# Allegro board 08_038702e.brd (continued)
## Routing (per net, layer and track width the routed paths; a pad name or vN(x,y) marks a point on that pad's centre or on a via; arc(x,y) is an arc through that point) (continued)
DDR3_DQ3: length 43.7
  TOP w0.197: U1.G26 v1(41.22,17.59)
  L17_SIG w0.14: v1(56.19,20.31) 56.07,20.31 55.68,19.92 54.54,19.92 54.15,19.54 54.15,15.86 54.92,15.09 54.92,10.78 54.66,10.52 50.09,10.52 49.84,10.78 49.84,11.16 50.09,11.41 53.39,11.41 53.65,11.67 53.65,14.38 53.67,14.4 53.67,15.08 53.14,15.6 53.14,19.67 52.88,19.92 49.33,19.92 48.36,18.95 44.07,18.95 43.85,18.74 43.85,18.64 43.23,18.02 41.64,18.02 v1(41.22,17.59)
  BOTTOM w0.197: U2.F8 v1(56.19,20.31)
DDR3_DQ4: length 43.5
  TOP w0.197: U1.H26 v1(40.22,17.59)
  L3_SIG w0.14: v1(40.22,17.59) 40.22,16.84 41.2,15.86 44.76,15.86 45.77,16.87 45.77,17.76 46.15,18.14 49.2,18.14 49.46,18.4 50.4,18.4 50.44,18.35 56.2,18.35 56.44,18.59 56.44,18.92 56.2,19.16 55.55,19.16 55.54,19.15 49.08,19.15 48.82,19.41 48.82,19.54 49.2,19.92 54.44,19.92 54.66,20.14 54.66,20.46 54.44,20.68 49.84,20.68 49.58,20.94 49.58,21.3 49.84,21.55 51.83,21.55 v1(52.19,21.91)
  BOTTOM w0.197: U2.H3 v1(52.19,21.91)
DDR3_DQ5: length 43.6
  TOP w0.197: U1.H23 v1(40.22,20.59)
  L4_SIG w0.14: v1(40.22,20.59) 40.22,20.59 40.69,21.06 47.3,21.06 47.93,20.43 48.82,20.43 49.46,21.06 49.86,21.06 50.34,21.55 54.52,21.55 55.3,22.33 55.9,22.33 56.72,23.15 57.14,23.15 57.35,23.36 57.35,25.38 57.61,25.64 57.97,25.64 58.22,25.38 58.22,23.73 58.44,23.51 58.63,23.51 58.85,23.73 58.85,24.67 59.19,25 59.66,25 60,24.67 60,24.62 60.38,24.24 61.39,24.24 62.01,23.62 64.19,23.62 64.57,23.24 64.57,22.59 64.19,22.21 62.54,22.21 61.88,22.86 61.88,22.99 61.52,23.35 60,23.35 59.62,22.97 58.22,22.97 57.96,22.71 57.2,22.71 56.95,22.46 56.95,22.38 56.48,21.91 v1(56.19,21.91)
  BOTTOM w0.197: U2.H8 v1(56.19,21.91)
DDR3_DQ6: length 43.4
  TOP w0.197: U1.J24 v1(39.22,19.59)
  L4_SIG w0.14: v1(39.22,19.59) 39.65,19.15 39.67,19.15 39.68,19.16 40.28,19.16 40.82,18.61 40.82,16.24 41.07,15.98 41.84,15.98 41.96,16.11 41.96,16.68 42.15,16.87 42.42,16.87 42.62,16.68 42.62,16.21 42.83,16 42.83,16 42.85,15.98 49.11,15.98 49.33,15.76 49.33,15.44 49.11,15.22 40.57,15.22 39.68,16.11 39.68,17.89 39.42,18.14 39.04,18.14 38.79,18.4 38.79,19.92 39.04,20.17 39.3,20.17 39.55,19.92 40.04,19.92 40.07,19.95 40.37,19.95 40.39,19.92 41.04,19.92 41.07,19.95 41.37,19.95 41.39,19.92 42.04,19.92 42.07,19.95 42.37,19.95 42.39,19.92 43.04,19.92 43.07,19.95 43.37,19.95 43.39,19.92 44.04,19.92 44.07,19.95 44.37,19.95 44.39,19.92 45.04,19.92 45.07,19.95 45.37,19.95 45.39,19.92 46.04,19.92 46.07,19.95 46.37,19.95 46.39,19.92 47.04,19.92 47.07,19.95 47.37,19.95 47.39,19.92 49.21,19.92 49.43,20.14 49.43,20.46 49.64,20.68 49.9,20.68 49.98,20.75 50.23,20.75 v1(50.59,21.11)
  BOTTOM w0.197: U2.G2 v1(50.59,21.11)
DDR3_DQ7: length 43.6
  TOP w0.197: U1.J23 v1(39.22,20.59)
  L17_SIG w0.14: v1(39.22,20.59) 38.8,20.17 32.18,20.17 31.8,19.79 31.8,16.36 31.55,16.11 30.91,16.11 30.89,16.13 30.89,16.13 30.68,16.34 30.68,16.35 30.66,16.36 30.66,20.81 31.08,21.23 36.41,21.23 36.61,21.42 36.87,21.42 37.07,21.23 37.1,21.23 47.37,21.23 47.62,21.48 52.34,21.48 52.37,21.44 52.88,21.44 53.35,21.91 v1(55.39,21.91)
  BOTTOM w0.197: U2.H7 v1(55.39,21.91)
DDR3_DQ8: length 44
  TOP w0.197: U1.K26 v1(38.22,17.59)
  L4_SIG w0.14: v1(38.22,17.59) 38.33,17.59 38.91,17 38.91,16.36 39.3,15.98 39.3,15.73 40.31,14.71 49.33,14.71 49.71,15.09 49.71,15.6 50.09,15.98 50.41,15.98 50.44,15.95 50.74,15.95 50.95,16.16 50.95,16.64 50.85,16.75 48.69,16.75 48.44,17 48.44,17.25 48.69,17.51 51.11,17.51 51.49,17.13 51.49,16.66 51.48,16.65 51.48,15.98 50.85,15.35 50.34,15.35 50.09,15.09 50.09,14.46 50.36,14.19 54,14.19 54.39,14.57 54.39,14.57 54.49,14.67 54.84,14.67 55.3,14.21 56.06,14.21 56.31,14.46 56.31,14.84 56.06,15.09 52.76,15.09 52.63,15.22 52.63,18.4 52.88,18.65 54.34,18.65 54.41,18.71 v1(55.39,18.71)
  BOTTOM w0.197: U2.D7 v1(55.39,18.71)
DDR3_DQ9: length 43.7
  TOP w0.197: U1.L23 v1(37.22,20.59)
  L6_SIG w0.14: v1(37.22,20.59) 36.74,21.06 35.1,21.06 33.71,22.46 33.71,23.73 34.09,24.11 41.45,24.11 41.84,23.73 41.84,21.23 42.12,20.95 42.57,20.95 42.85,21.23 42.85,22.74 43.34,23.23 43.37,23.23 43.58,23.44 43.58,23.44 43.68,23.54 43.68,24.97 43.83,25.13 45.64,25.13 45.85,24.91 45.85,24.37 45.6,24.11 45.14,24.11 44.58,23.55 44.58,23.44 44.37,23.23 44.25,23.23 43.58,22.55 43.58,20.46 43.82,20.23 46.75,20.23 46.97,20 47.72,20 48.57,19.15 50.74,19.15 50.75,19.16 52.04,19.16 52.04,19.15 52.34,19.15 52.35,19.16 53.46,19.16 53.65,18.97 53.65,18.71 53.46,18.52 52.76,18.52 52.63,18.65 52.26,18.65 v1(52.19,18.71)
  BOTTOM w0.197: U2.C3 v1(52.19,18.71)
DDR3_DQ10: length 43.8
  TOP w0.197: U1.M26 v1(36.22,17.59)
  L7_SIG w0.14: v6(56.19,17.94) 56.19,17.91 56.63,17.48 57.07,17.48 57.36,17.76 58.47,17.76 58.73,17.51 58.73,16.75 58.98,16.49 59.23,16.49 59.51,16.77 59.51,17.51 59.76,17.76 60.89,17.76 61.14,18.02 61.14,19.67 60.89,19.92 58.85,19.92 58.47,19.54 58.47,18.78 58.05,18.35 55.93,18.35 55.81,18.23 55.81,17.76 55.55,17.51 55.3,17.51 54.79,17 54.79,15.98 55.04,15.73 55.3,15.73 55.68,15.35 55.68,13.82 55.42,13.57 49.33,13.57 48.57,14.33 47.17,14.33 46.04,15.46 42.99,15.46 42.6,15.86 40.57,15.86 39.69,16.73 38.04,16.73 37.92,16.85 37.62,16.85 37.5,16.73 36.74,16.73 36.22,17.25 v1(36.22,17.59)
  BOTTOM w0.197: v6(56.19,17.94) 56.17,17.94 U2.C8
DDR3_DQ11: length 43.6
  TOP w0.197: U1.K23 v1(38.22,20.59)
  L6_SIG w0.14: v1(38.22,20.59) 38.25,20.56 38.66,20.56 38.79,20.68 38.79,21.06 38.66,21.19 38.03,21.19 37.77,20.94 37.77,20.3 37.64,20.17 37.14,20.17 36.85,19.89 36.85,19.44 37.07,19.23 39.37,19.23 39.42,19.29 39.47,19.29 39.85,19.67 39.85,21.74 39.39,22.21 34.6,22.21 34.09,22.71 34.09,23.1 34.22,23.22 40.31,23.22 40.69,22.84 40.69,19.67 40.85,19.51 40.85,19.41 41.1,19.16 41.46,19.16 41.71,19.41 41.71,19.62 42.01,19.92 42.04,19.92 42.07,19.95 42.37,19.95 42.4,19.92 42.43,19.92 42.72,19.62 42.72,19.54 43.04,19.23 47.74,19.23 48.57,18.4 49.33,18.4 49.45,18.28 52.04,18.28 52.41,18.28 52.63,18.05 52.63,17.73 52.41,17.51 51.02,17.51 50.83,17.69 50.81,17.69 v1(50.59,17.91)
  BOTTOM w0.197: U2.C2 v1(50.59,17.91)
DDR3_DQ12: length 43.9
  TOP w0.197: U1.M25 v1(36.22,18.59)
  L15_SIG w0.14: v1(36.22,18.59) 36.22,18.62 36.76,19.16 38.46,19.16 38.71,19.41 38.71,20.77 39.01,21.06 39.43,21.06 39.73,20.77 39.73,15.63 40.01,15.35 40.41,15.35 40.69,15.63 40.69,20.65 41.13,21.08 41.34,21.08 41.58,20.85 41.58,17.46 41.91,17.13 42.39,17.13 42.72,17.46 42.72,20.81 43.11,21.19 44.13,21.19 44.58,20.74 44.58,20.73 44.88,20.43 44.88,19.77 44.85,19.74 44.85,18.43 45.33,17.95 45.37,17.95 45.58,17.74 45.58,17.7 46.15,17.13 48.19,17.13 48.57,17.51 53.06,17.51 54.31,16.26 v1(55.39,16.26)
  BOTTOM w0.197: v1(55.39,16.26) 55.39,16.31 U2.A7
DDR3_DQ13: length 43.8
  TOP w0.197: U1.N24 v1(35.22,19.59)
  L3_SIG w0.14: v1(35.22,19.59) 35.22,19.75 34.92,20.05 34.72,20.05 34.6,19.92 34.6,17 34.45,16.85 33.94,16.85 33.73,16.64 33.73,16.64 33.63,16.54 33.63,16.34 33.85,16.12 36.26,16.12 36.5,16.36 36.5,16.58 36.67,16.75 37.51,16.75 37.62,16.85 37.92,16.85 38.03,16.75 38.66,16.75 39.93,15.48 39.93,13.06 40.18,12.81 40.82,12.81 40.93,12.7 40.93,12.28 40.72,12.07 40.71,12.07 40.57,11.92 40.57,11.67 40.82,11.41 43.49,11.41 43.61,11.54 43.61,11.79 43.49,11.92 42.34,11.92 41.96,12.3 41.96,12.55 42.22,12.81 44.12,12.81 44.52,12.41 44.52,12.28 44.73,12.07 53.29,12.07 53.53,12.3 53.53,13.18 52.76,13.95 52.76,14.84 53.01,15.09 53.27,15.09 53.52,15.35 53.52,15.86 53.27,16.11 51.36,16.11 51.16,16.31 v1(50.59,16.31)
  BOTTOM w0.197: U2.A2 v1(50.59,16.31)
DDR3_DQ14: length 43.8
  TOP w0.197: U1.M24 v1(36.22,19.59)
  L3_SIG w0.14: v1(36.22,19.59) 36.22,19.19 36.85,18.55 36.85,18.44 37.07,18.23 37.18,18.23 37.39,18.02 38.53,18.02 38.85,17.7 38.85,17.44 39.07,17.23 39.32,17.23 39.55,17 39.55,16.87 40.69,15.73 40.69,14.21 40.95,13.95 47.42,13.95 47.68,14.21 47.68,14.46 47.42,14.71 41.54,14.71 41.33,14.92 41.33,15.22 41.54,15.43 45.05,15.43 45.15,15.33 47.99,15.33 48.19,15.52 48.19,15.79 47.99,15.98 46.66,15.98 46.41,16.24 46.41,16.87 46.66,17.13 47.3,17.13 47.68,17.51 55.3,17.51 v3(55.69,17.11)
  L19_GND w0.14: v4(56.19,17.11) v3(55.69,17.11)
  BOTTOM w0.197: v4(56.19,17.11) U2.B8
DDR3_DQ15: length 43.7
  TOP w0.197: U1.N23 v1(35.22,20.59)
  L3_SIG w0.14: v1(35.22,20.59) 35.22,20.57 35.61,20.17 35.61,18.68 36.07,18.23 36.16,18.23 36.85,17.54 36.85,17.44 37.07,17.23 37.16,17.23 37.26,17.13 38.79,17.13 40.31,15.6 40.31,13.57 40.69,13.19 41.11,13.19 41.28,13.02 41.79,13.02 42.09,13.32 43.74,13.32 43.98,13.08 44.27,13.08 44.33,13.02 45.31,13.02 45.75,12.58 45.75,12.57 45.9,12.43 46.28,12.43 46.66,12.81 46.66,13.19 46.92,13.44 47.68,13.44 47.93,13.19 47.93,12.55 48.06,12.43 48.69,12.43 48.82,12.55 48.82,13.19 49.07,13.44 49.71,13.44 49.96,13.19 49.96,12.68 50.22,12.43 50.85,12.43 51.11,12.68 51.11,13.19 51.36,13.44 52.25,13.44 52.37,13.56 52.37,13.72 52.13,13.95 50.34,13.95 50.22,13.82 48.31,13.82 48.19,13.95 48.19,14.33 48.31,14.46 52.25,14.46 52.49,14.7 52.49,14.95 52.5,14.96 52.5,15.48 52.25,15.73 50.34,15.73 50.15,15.92 50.15,16.55 50.34,16.75 51.61,16.75 v3(51.87,16.49)
  L19_GND w0.14: v4(51.39,16.31) 51.69,16.31 v3(51.87,16.49)
  BOTTOM w0.197: U2.A3 v4(51.39,16.31)
DDR3_DQ16: length 46
  TOP w0.197: U1.R26 v1(32.22,17.59)
  L15_SIG w0.14: v1(32.22,17.59) 31.8,18 30.96,18 30.66,18.3 30.66,18.73 30.96,19.03 31.42,19.03 31.8,19.41 31.8,25.76 32.27,26.23 32.37,26.23 32.58,26.44 32.58,26.54 33.27,27.23 35.42,27.23 35.74,26.91 35.74,26.55 36.07,26.23 36.46,26.23 36.63,26.4 36.63,27.79 36.88,28.05 37.39,28.05 37.64,27.79 37.9,27.79 38.03,27.92 38.03,28.27 38.01,28.28 37.77,28.52 37.77,28.94 38.03,29.19 38.41,29.19 38.53,29.06 39.2,29.06 39.58,29.44 39.58,29.74 39.37,29.95 39.3,29.95 39.3,29.95 38.8,29.95 38.68,30.08 38.68,30.21 38.55,30.33 38.15,30.33 38.03,30.46 38.03,30.97 38.15,31.1 39.37,31.1 39.59,31.32 39.59,31.82 39.42,31.99 38.8,31.99 38.68,32.11 38.68,32.56 39.07,32.95 39.12,32.95 39.85,33.69 39.85,33.74 40.07,33.95 40.12,33.95 40.85,34.69 40.85,34.74 41.07,34.95 41.12,34.95 41.85,35.69 41.85,35.74 42.07,35.95 42.12,35.95 42.85,36.69 42.85,36.74 43.07,36.95 43.12,36.95 43.36,37.19 48.95,37.19 49.46,37.7 50.26,37.7 50.52,37.44 50.74,37.44 51.03,37.15 51.03,36.73 51.02,36.72 v1(51.39,36.34)
  BOTTOM w0.197: U3.E3 51.46,36.34 v1(51.39,36.34)
DDR3_DQ17: length 45.8
  TOP w0.197: U1.P24 v1(33.22,19.59)
  L7_SIG w0.14: v1(55.39,37.14) 55.33,37.08 54.68,37.08 53.39,35.8 53.39,33.38 53.27,33.26 52.12,33.26 51.75,32.89 51.75,32.87 51.54,32.65 49.96,32.65 49.93,32.62 49.33,32.62 48.82,33.13 46.96,33.13 46.66,33.43 46.66,34.86 46.36,35.16 45.94,35.16 45.65,34.86 45.65,32.62 45.77,32.49 45.77,29.36 45.47,29.06 45.05,29.06 44.76,29.36 44.76,31.86 44.5,32.11 44.12,32.11 43.87,31.86 43.87,31.75 43.85,31.74 43.85,31.44 43.87,31.43 43.87,30.75 43.85,30.74 43.85,30.44 43.87,30.43 43.87,29.75 43.85,29.74 43.85,29.3 43.61,29.06 40.18,29.06 39.85,28.74 39.85,28.7 39.11,27.95 39.07,27.95 38.85,27.74 38.85,27.7 38.11,26.95 38.07,26.95 37.85,26.74 37.85,26.7 37.11,25.95 37.07,25.95 36.85,25.74 36.85,25.7 36.11,24.95 36.07,24.95 35.85,24.74 35.85,24.7 35.84,24.69 35.84,24.33 35.47,23.95 35.07,23.95 34.58,23.47 34.58,20.96 v1(33.22,19.59)
  BOTTOM w0.197: v1(55.39,37.14) 55.33,37.14 U3.F7
DDR3_DQ18: length 45.7
  TOP w0.197: U1.N26 v1(35.22,17.59)
  L15_SIG w0.14: v1(50.59,37.08) 50.3,37.08 49.87,36.65 49.52,36.65 49.17,36.3 49.17,35.95 48.77,35.54 47.8,35.54 47.3,36.05 43.36,36.05 43.26,35.95 43.07,35.95 42.85,35.74 42.85,35.54 42.26,34.95 42.07,34.95 41.85,34.74 41.85,34.54 41.26,33.95 41.07,33.95 40.85,33.74 40.85,33.54 40.26,32.95 40.07,32.95 39.85,32.74 39.85,31.43 40.31,30.97 40.31,30.33 39.85,29.88 39.85,28.73 39.58,28.46 39.58,28.44 39.37,28.23 39.34,28.23 38.85,27.74 38.85,27.72 38.37,27.23 38.34,27.23 37.85,26.74 37.85,26.72 37.65,26.52 37.65,26.24 37.37,25.95 34.92,25.95 34.72,26.14 34.72,26.65 34.6,26.78 33.96,26.78 33.49,26.31 33.49,26.11 33.83,25.76 33.83,25.38 33.58,25.13 32.95,25.13 32.69,24.87 32.69,24.37 32.95,24.11 33.58,24.11 33.83,23.86 33.83,23.35 33.58,23.1 32.95,23.1 32.69,22.84 32.69,22.33 32.95,22.08 33.58,22.08 33.83,21.83 33.83,21.32 33.58,21.06 32.95,21.06 32.69,20.81 32.69,20.3 32.82,20.17 33.58,20.17 33.83,19.92 33.83,19.29 33.71,19.16 32.95,19.16 32.69,18.9 32.69,18.27 32.95,18.02 33.58,18.02 33.71,18.14 33.71,18.65 33.83,18.78 34.03,18.78 v1(35.22,17.59)
  BOTTOM w0.197: U3.F2 v1(50.59,37.08)
DDR3_DQ19: length 45.8
  TOP w0.197: U1.P23 v1(33.22,20.59)
  L7_SIG w0.14: v1(33.22,20.59) 33.46,20.59 34.05,21.18 34.05,23.88 34.6,24.43 34.6,25.35 34.85,25.6 34.85,25.74 35.07,25.95 35.2,25.95 35.85,26.6 35.85,26.74 36.34,27.23 36.37,27.23 36.58,27.44 36.58,27.46 37.34,28.23 37.37,28.23 37.85,28.71 37.85,30.04 39.04,31.23 39.37,31.23 39.58,31.44 39.58,31.74 40.07,32.23 40.37,32.23 40.58,32.44 40.58,32.76 40.95,33.13 41.45,33.13 41.71,33.38 41.71,37.83 41.96,38.08 43.61,38.08 43.85,38.32 43.85,38.74 43.87,38.75 43.87,38.84 44.12,39.1 48.82,39.1 49.07,38.84 49.07,36.3 49.54,35.84 51.53,35.84 52.63,36.94 52.63,37.07 53.53,37.97 54.43,37.97 54.92,38.46 54.92,39.1 55.3,39.48 56.35,39.48 56.57,39.26 56.57,37.45 56.26,37.14 v1(56.19,37.14)
  BOTTOM w0.197: v1(56.19,37.14) 56.13,37.14 U3.F8
DDR3_DQ20: length 46.2
  TOP w0.197: U1.T24 v1(31.22,19.59)
  L7_SIG w0.14: v1(31.22,19.59) 31.55,19.92 31.55,20.17 31.85,20.48 31.85,20.74 32.07,20.95 32.58,20.95 32.85,21.23 32.85,24.74 33.07,24.95 33.28,24.95 33.83,25.51 33.83,26.52 34.72,27.41 34.72,27.61 35.34,28.23 35.37,28.23 35.58,28.44 35.58,28.46 36.07,28.95 36.26,28.95 36.63,29.32 36.63,30.46 37.85,31.69 37.85,31.74 38.07,31.95 38.12,31.95 38.85,32.69 38.85,32.74 39.07,32.95 39.12,32.95 39.68,33.51 39.68,39.86 40.04,40.23 43.37,40.23 43.85,40.71 43.85,40.74 44.07,40.95 44.32,40.95 44.5,41.13 47.8,41.13 48.59,41.91 48.59,42.17 48.8,42.38 49.22,42.38 50.23,41.37 50.23,40.13 50.44,39.92 50.44,39.04 50.23,38.83 50.23,37.73 50.51,37.45 52.25,37.45 52.5,37.7 52.5,38.46 52.25,38.72 51.43,38.72 v1(51.39,38.68)
  BOTTOM w0.197: U3.H3 v1(51.39,38.68)
DDR3_DQ21: length 45.9
  TOP w0.197: U1.T25 v1(31.22,18.59)
  L7_SIG w0.14: v1(31.22,18.59) 31.68,19.05 32.33,19.05 32.82,19.54 32.82,19.82 33.2,20.2 33.45,20.2 34.32,21.07 34.32,23.58 34.96,24.23 35.37,24.23 35.58,24.44 35.58,25.47 36.33,26.23 36.37,26.23 36.58,26.44 36.58,26.47 37.33,27.23 37.37,27.23 37.58,27.44 37.58,27.47 38.33,28.23 38.37,28.23 38.58,28.44 38.58,28.47 39.33,29.23 39.37,29.23 39.58,29.44 39.58,29.47 40.18,30.08 41.54,30.08 41.71,30.24 41.71,32.75 41.96,33 42.47,33 42.72,33.26 42.72,36.68 42.98,36.94 43.05,36.94 43.07,36.95 43.37,36.95 43.38,36.94 44.05,36.94 44.07,36.95 44.37,36.95 44.38,36.94 45.05,36.94 45.07,36.95 45.37,36.95 45.38,36.94 46.05,36.94 46.07,36.95 46.37,36.95 46.38,36.94 46.6,36.94 46.85,36.68 46.85,36.44 47.07,36.23 47.11,36.23 47.37,35.97 47.37,35.95 47.58,35.74 47.58,35.13 48.06,34.65 49.31,34.65 49.58,34.38 49.58,33.77 49.84,33.52 52,33.52 52.88,34.4 52.88,36.18 53.27,36.56 53.27,37.26 53.71,37.71 54.67,37.71 54.79,37.83 55.93,37.83 56.19,38.08 56.19,38.67 v1(56.19,38.68)
  BOTTOM w0.197: U3.H8 v1(56.19,38.68)
DDR3_DQ22: length 46
  TOP w0.197: U1.T23 v1(31.22,20.59)
  L7_SIG w0.14: v1(31.22,20.59) 31.85,21.23 32.37,21.23 32.59,21.45 32.59,25.53 32.95,25.89 32.95,26.35 32.85,26.44 32.85,26.74 33.07,26.95 33.37,26.95 34.34,27.92 34.34,28.23 35.07,28.95 35.12,28.95 35.23,29.06 35.36,29.06 35.85,29.56 35.85,29.74 36.12,30.01 36.12,30.97 36.85,31.7 36.85,31.74 37.07,31.95 37.1,31.95 37.85,32.7 37.85,32.74 38.07,32.95 38.1,32.95 38.85,33.7 38.85,40.81 39.27,41.23 43.46,41.23 43.85,41.62 43.85,42 43.99,42.15 48.06,42.15 48.31,42.4 48.31,43.59 48.57,43.84 50.74,43.84 50.95,43.63 50.95,41.23 51.03,41.15 51.03,40.13 51.24,39.92 51.24,39.03 51.03,38.83 51.03,38.01 50.9,37.88 v1(50.59,37.88)
  BOTTOM w0.197: U3.G2 v1(50.59,37.88)
DDR3_DQ23: length 46
  TOP w0.197: U1.R23 v1(32.22,20.59)
  L7_SIG w0.14: v1(32.22,20.59) 32.7,20.59 33.07,20.95 33.09,20.95 33.78,21.64 33.78,24.91 34.22,25.34 34.22,26.02 34.85,26.65 34.85,26.74 35.07,26.95 35.15,26.95 35.85,27.65 35.85,27.74 36.07,27.95 36.23,27.95 36.85,28.57 36.85,28.74 37.07,28.95 37.09,28.95 37.58,29.44 37.58,29.74 37.37,29.95 37.37,30.42 38.17,31.23 38.37,31.23 38.58,31.44 38.58,31.65 39.16,32.23 39.37,32.23 39.58,32.44 39.58,32.65 40.16,33.23 40.37,33.23 40.58,33.44 40.58,38.86 40.95,39.23 43.37,39.23 43.58,39.44 43.58,39.57 44.12,40.11 47.68,40.11 48.19,40.62 48.19,40.88 48.57,41.26 48.95,41.26 49.96,40.24 49.96,39.99 49.43,39.45 49.43,36.92 49.46,36.89 49.46,36.68 49.84,36.3 50.47,36.3 50.85,36.68 51.22,36.68 51.24,36.7 51.54,36.7 51.56,36.68 51.87,36.68 53.88,38.7 53.88,38.82 54.15,39.1 54.3,39.1 54.45,38.95 54.45,38.76 v1(54.29,38.6)
  BOTTOM w0.197: U3.H7 54.52,38.6 v1(54.29,38.6)
DDR3_DQ24: length 43.7
  TOP w0.197: U1.V24 v1(29.22,19.59)
  L4_SIG w0.14: v3(33.96,31.6) 33.96,31.73 33.71,31.99 31.93,31.99 31.68,31.73 31.68,31.35 31.93,31.1 32.18,31.1 32.44,30.84 32.44,30.46 31.93,29.95 31.93,29.81 31.85,29.74 31.85,29.62 31.18,28.95 31.07,28.95 30.85,28.74 30.85,28.5 30.41,28.05 30.1,28.05 29.59,27.54 29.59,19.96 v1(29.22,19.59)
  L6_SIG w0.14: v3(33.96,31.6) 34.85,30.72 34.98,30.72 35.85,31.59 35.85,31.74 36.07,31.95 36.21,31.95 36.85,32.59 36.85,32.74 37.07,32.95 37.21,32.95 37.85,33.59 37.85,33.74 38.07,33.95 38.21,33.95 38.85,34.59 38.85,34.74 39.07,34.95 39.21,34.95 39.85,35.59 39.85,35.74 40.07,35.95 40.21,35.95 40.85,36.59 40.85,36.74 41.18,37.07 47.55,37.07 47.93,36.68 51.22,36.68 51.24,36.7 53.63,36.7 54.79,35.54 v1(55.39,35.54)
  BOTTOM w0.197: v1(55.39,35.54) 55.33,35.54 U3.D7
DDR3_DQ25: length 43.8
  TOP w0.197: U1.U26 v1(30.22,17.59)
  L3_SIG w0.14: v1(51.39,34.68) 51.03,34.32 51.03,33.73 50.81,33.51 49.71,33.51 49.7,33.52 49.64,33.52 49.43,33.73 49.43,34.53 49.18,34.78 48.69,34.78 48.44,34.53 48.44,22.33 47.58,21.47 47.58,21.44 47.37,21.23 47.33,21.23 46.58,20.47 46.58,20.44 46.37,20.23 46.33,20.23 45.58,19.47 45.58,19.44 45.37,19.23 45.33,19.23 44.58,18.47 44.58,18.44 44.37,18.23 41.07,18.23 40.85,18.44 40.85,18.74 40.37,19.23 40.07,19.23 39.85,19.44 39.85,19.74 39.37,20.23 39.07,20.23 38.85,20.44 38.85,20.65 38.28,21.23 38.07,21.23 37.85,21.44 37.85,21.53 37.8,21.58 37.83,21.61 37.83,21.84 37.47,22.21 34.47,22.21 33.49,21.23 32.09,21.23 31.58,20.71 31.58,19.44 31.37,19.23 31.23,19.23 30.79,18.78 30.79,18.14 30.23,17.59 v1(30.22,17.59)
  BOTTOM w0.197: U3.C3 v1(51.39,34.68)
DDR3_DQ26: length 43.6
  TOP w0.197: U1.U24 v1(30.22,19.59)
  L4_SIG w0.14: v1(30.22,19.59) 29.85,19.95 29.85,26.74 30.07,26.95 30.15,26.95 30.85,27.65 30.85,27.74 31.07,27.95 31.15,27.95 31.27,28.07 32.46,28.07 32.82,28.43 32.82,28.81 32.56,29.06 32.56,29.45 32.82,29.7 32.82,30.97 33.07,31.22 33.58,31.22 33.83,30.97 v3(33.83,29.57)
  L6_SIG w0.14: v1(56.19,34.61) 55.9,34.61 55.54,34.25 54.55,34.25 54.52,34.28 52.3,34.28 51.54,35.04 47.65,35.04 47.48,35.22 40.24,35.22 39.58,34.55 39.58,34.44 39.37,34.23 39.25,34.23 38.58,33.55 38.58,33.44 38.37,33.23 38.25,33.23 37.58,32.55 37.58,32.44 37.37,32.23 37.25,32.23 36.58,31.55 36.58,31.44 36.37,31.23 36.25,31.23 35.36,30.33 33.97,30.33 33.83,30.19 v3(33.83,29.57)
  BOTTOM w0.197: U3.C8 56.19,34.68 v1(56.19,34.61)
DDR3_DQ27: length 43.8
  TOP w0.197: U1.U25 v1(30.22,18.59)
  L3_SIG w0.14: v1(30.22,18.59) 30.22,18.59 30.66,19.03 30.66,21.7 30.91,21.95 33.45,21.95 34.6,23.1 36.76,23.1 36.88,22.97 37.35,22.97 37.58,22.74 37.58,22.48 38.1,21.96 38.1,21.95 38.53,21.95 38.85,21.63 38.85,21.44 39.07,21.23 39.26,21.23 39.85,20.63 39.85,20.44 40.07,20.23 40.26,20.23 40.85,19.63 40.85,19.44 41.13,19.16 43.33,19.16 43.51,18.98 44.63,18.98 44.85,19.2 44.85,19.76 45.32,20.23 45.37,20.23 45.44,20.3 45.58,20.3 45.58,20.61 46.19,21.23 46.37,21.23 46.58,21.44 46.58,21.61 47.19,22.23 47.37,22.23 47.58,22.44 47.58,22.61 48.06,23.1 48.06,35.54 48.31,35.8 49.98,35.8 50.02,35.84 50.74,35.84 50.98,35.6 50.98,35.07 v1(50.59,34.68)
  BOTTOM w0.197: U3.C2 v1(50.59,34.68)
DDR3_DQ28: length 43.5
  TOP w0.197: U1.W26 v1(28.22,17.59)
  L7_SIG w0.14: v1(55.39,33.08) 55.43,33.08 55.79,32.72 55.8,32.72 56.55,31.96 56.55,27.36 56.34,27.15 56.06,27.15 55.75,26.85 55.75,26.56 55.75,26.5 55.54,26.29 55.32,26.29 54.52,25.49 54.13,25.49 53.32,24.68 52.04,24.68 51.24,23.88 49.64,23.88 49.46,23.69 47.62,23.69 47.37,23.95 47.07,23.95 46.85,23.74 46.58,23.74 46.37,23.95 44.07,23.95 43.85,23.74 43.85,23.37 43.44,22.95 43.07,22.95 42.58,22.46 42.58,22.44 42.09,21.95 42.07,21.95 41.58,21.46 41.58,21.44 41.09,20.95 41.07,20.95 40.85,20.74 40.85,20.72 40.58,20.44 40.58,20.44 40.37,20.23 40.34,20.23 39.85,19.74 39.85,19.72 39.37,19.23 39.34,19.23 38.85,18.74 38.85,18.72 38.36,18.23 36.33,18.23 35.85,17.75 35.85,17.44 35.87,17.43 35.87,16.75 35.59,16.47 35.59,16.34 35.38,16.13 35.25,16.13 34.47,15.35 31.8,15.35 31.42,15.73 29.77,15.73 29.37,16.13 29.37,16.13 29.15,16.34 29.15,16.34 28.75,16.75 28.75,17 28.22,17.54 v1(28.22,17.59)
  BOTTOM w0.197: U3.A7 v1(55.39,33.08)
DDR3_DQ29: length 43.9
  TOP w0.197: U1.Y25 v1(27.22,18.59)
  L15_SIG w0.14: v1(27.22,18.59) 27.3,18.59 27.93,19.23 28.37,19.23 28.58,19.44 28.58,19.46 29.07,19.95 29.16,19.95 29.85,20.64 29.85,20.74 30.34,21.23 30.37,21.23 30.58,21.44 30.58,25.47 30.84,25.74 30.85,25.74 31.07,25.95 31.09,25.95 31.85,26.72 31.85,26.74 32.07,26.95 32.09,26.95 32.69,27.55 32.69,27.58 33.08,27.96 36.03,27.96 36.3,28.23 36.37,28.23 36.58,28.44 36.58,28.5 37.3,29.23 37.37,29.23 37.58,29.44 37.58,32.46 38.07,32.95 38.23,32.95 38.85,33.58 38.85,33.74 39.07,33.95 39.23,33.95 39.85,34.58 39.85,34.74 40.07,34.95 40.23,34.95 40.85,35.58 40.85,35.74 41.07,35.95 41.23,35.95 41.85,36.58 41.85,36.74 42.07,36.95 42.23,36.95 42.85,37.58 42.85,37.74 43.07,37.95 43.23,37.95 50.44,38.24 50.74,38.24 50.95,38.03 50.95,37.98 51.03,37.9 51.03,37.73 51.24,37.52 51.54,37.52 51.74,37.32 51.74,37.24 51.75,37.23 51.75,36.93 51.74,36.92 51.74,36.5 51.75,36.49 51.75,35.27 51.74,35.25 51.74,34.84 51.75,34.83 51.75,34.53 51.74,34.52 v1(50.59,33.01)
  BOTTOM w0.197: v1(50.59,33.01) 50.59,33.08 U3.A2
DDR3_DQ30: length 43.8
  TOP w0.197: U1.Y26 v1(27.22,17.59)
  L4_SIG w0.14: v1(27.22,17.59) 27.22,17.62 27.74,18.14 27.74,21.6 27.85,21.72 27.85,21.74 28.34,22.23 28.37,22.23 28.58,22.44 28.58,27.49 29.31,28.23 29.37,28.23 29.85,28.72 29.85,28.74 30.07,28.95 v3(30.66,29.19)
  L6_SIG w0.14: v1(56.19,33.88) 56.17,33.88 55.81,33.51 54.92,33.51 54.41,34.02 51.23,34.02 50.93,34.32 48.1,34.32 47.93,34.49 47.82,34.49 47.37,34.95 40.8,34.95 40.58,34.73 40.58,34.44 40.37,34.23 40.08,34.23 39.58,33.73 39.58,33.44 39.37,33.23 39.08,33.23 38.58,32.73 38.58,32.44 38.37,32.23 38.08,32.23 37.58,31.73 37.58,31.44 37.37,31.23 37.08,31.23 35.8,29.95 35.36,29.95 35.35,29.95 34.85,29.95 34.09,29.19 v3(30.66,29.19)
  BOTTOM w0.197: U3.B8 v1(56.19,33.88)
DDR3_DQ31: length 43.6
  TOP w0.197: U1.W23 v1(28.22,20.59)
  L15_SIG w0.14: v1(51.39,33.01) 52.5,34.13 52.5,38.08 51.36,39.22 43.36,39.22 43.08,38.95 43.07,38.95 42.85,38.74 42.85,38.72 42.37,38.23 42.34,38.23 41.85,37.74 41.85,37.72 41.37,37.23 41.34,37.23 40.85,36.74 40.85,36.72 40.37,36.23 40.34,36.23 39.85,35.74 39.85,35.72 39.37,35.23 39.34,35.23 38.85,34.74 38.85,34.72 38.37,34.23 38.34,34.23 37.85,33.74 37.85,33.72 37.37,33.23 37.34,33.23 36.63,32.51 36.63,29.51 36.58,29.46 36.58,29.44 36.37,29.23 36.34,29.23 36.05,28.94 35.38,28.94 35.37,28.95 35.07,28.95 35.05,28.94 33.38,28.94 33.37,28.95 33.07,28.95 32.85,28.74 32.85,28.72 32.09,27.95 32.07,27.95 31.84,27.72 31.83,27.72 31.58,27.47 31.58,27.44 31.09,26.95 31.07,26.95 30.85,26.74 30.85,26.72 30.09,25.95 30.07,25.95 29.85,25.74 29.85,25.72 29.64,25.51 29.64,21.57 29.58,21.5 29.58,21.44 29.37,21.23 29.3,21.23 28.66,20.59 v1(28.22,20.59)
  BOTTOM w0.197: v1(51.39,33.01) 51.39,33.08 U3.A3
DDR3_DQS0_N: length 43.5
  TOP w0.152: U1.G25 v1(41.22,18.59)
  L4_SIG w0.13: v1(41.22,18.59) 40.9,18.91 40.95,18.96 41.47,18.96 41.48,18.96 42.79,18.96 42.81,18.98 43.72,18.98 43.74,18.96 44.35,18.96 44.57,18.74 44.57,17 44.82,16.75 45.42,16.75 45.86,17.18 45.86,18.74 46.07,18.95 46.14,18.95 46.15,18.96 46.17,18.95 46.36,18.95 46.57,18.74 46.57,17.17 47,16.75 47.36,16.75 47.36,16.74 47.57,16.74 47.93,17.11 47.93,18.7 48.19,18.96 49.09,18.96 49.29,19.16 52.34,19.16 52.55,19.37 52.55,19.38 52.58,19.41 54.99,19.41 55.24,19.16 57.14,19.16 57.4,19.41 58.12,19.41 58.62,19.92 59.87,19.92 60.5,19.29 61.01,19.29 61.52,19.79 61.52,20.99 61.38,21.13 61.38,21.43 61.4,21.44 61.4,22.08 60.99,22.48 58.37,22.48 57.96,22.08 57.96,21.57 57.86,21.47 55.24,21.47 54.97,21.19 53.41,21.19 53.33,21.11 v1(52.19,21.11)
  BOTTOM w0.152: U2.G3 v1(52.19,21.11)
DDR3_DQS0_P: length 43.6
  TOP w0.152: U1.H24 v1(40.22,19.59)
  L4_SIG w0.13: v1(52.19,20.31) 52.74,20.86 53.44,20.86 53.52,20.94 55.07,20.94 55.24,20.76 57.14,20.76 57.44,21.06 57.82,21.06 58.22,21.47 58.22,21.97 58.47,22.23 60.89,22.23 61.14,21.97 61.14,21.55 61.12,21.53 61.12,21.02 61.26,20.88 61.26,19.9 60.91,19.54 60.61,19.54 59.98,20.18 58.52,20.18 58.01,19.67 57.34,19.67 57.14,19.87 55.24,19.87 55.04,19.67 52.54,19.67 52.34,19.87 49.64,19.87 48.99,19.21 48.08,19.21 47.67,18.81 47.67,17.21 47.46,17 47.11,17 46.83,17.28 46.83,18.84 46.47,19.2 46.27,19.2 46.26,19.21 46.15,19.21 ; v1(40.22,19.59) 40.53,19.27 41.01,19.27 41.06,19.22 41.58,19.22 41.59,19.21 42.69,19.21 42.7,19.23 43.83,19.23 43.85,19.21 44.46,19.21 44.83,18.84 44.83,17.1 44.93,17 45.31,17 45.6,17.29 45.6,18.84 45.96,19.2 46.03,19.2 46.05,19.21 ; 46.05,19.21 46.15,19.21 ; 46.05,19.21 46.15,19.21
  BOTTOM w0.152: U2.F3 v1(52.19,20.31)
DDR3_DQS1_N: length 43.8
  TOP w0.152: U1.L25 v1(37.22,18.59)
  L4_SIG w0.13: v1(37.22,18.59) 37.22,18.87 37.46,19.12 37.64,19.12 37.77,19 37.77,18.52 37.41,18.16 37.41,17.9 37.57,17.74 37.57,17.44 37.36,17.23 37.22,17.23 36.5,16.51 36.5,15.33 37.62,14.21 48.67,14.21 49.05,13.83 56.46,13.83 57.48,14.84 58.62,14.84 58.85,15.07 58.85,17.43 58.62,17.66 58.2,17.66 57.97,17.43 57.97,16 57.44,15.47 53.52,15.47 53.14,15.85 53.14,16.49 53.52,16.87 54.54,16.87 54.92,17.25 54.92,17.59 54.59,17.91 v1(54.59,17.94)
  BOTTOM w0.152: U2.B7 54.59,17.91 v1(54.59,17.94)
DDR3_DQS1_P: length 43.9
  TOP w0.152: U1.L24 v1(37.22,19.59)
  L4_SIG w0.13: v6(55.39,17.94) 55.39,17.91 55.17,17.69 55.17,17.15 54.64,16.62 53.63,16.62 53.39,16.39 53.39,15.96 53.63,15.73 57.33,15.73 57.71,16.11 57.71,17.53 58.09,17.91 58.73,17.91 59.11,17.53 59.11,14.97 58.73,14.59 57.58,14.59 56.57,13.57 48.95,13.57 48.57,13.95 37.52,13.95 36.25,15.22 36.25,16.62 36.85,17.22 36.85,17.74 36.88,17.78 36.88,18.4 36.85,18.44 36.85,18.74 36.88,18.78 36.88,18.9 37.22,19.24 v1(37.22,19.59)
  BOTTOM w0.152: v6(55.39,17.94) 55.37,17.94 U2.C7
DDR3_DQS2_N: length 46
  TOP w0.152: U1.R25 v1(32.22,18.59)
  L3_SIG w0.13: v1(32.22,18.59) 32.57,17.98 32.57,17.25 32.95,16.87 33.56,16.87 34.22,17.53 34.22,20.1 35.07,20.95 37.36,20.95 37.6,20.71 37.6,20.65 37.6,20.33 37.86,20.07 37.86,20.07 37.96,19.98 37.97,19.98 38,19.95 38.36,19.95 38.6,19.71 38.6,19.33 38.96,18.98 39.33,18.98 39.6,18.71 39.6,18.33 39.99,17.95 40.36,17.95 40.57,17.74 40.57,17.26 40.97,16.87 44.36,16.87 44.83,17.33 44.83,17.74 45.07,17.98 45.47,17.98 45.83,18.33 45.83,18.74 46.07,18.98 46.47,18.98 46.83,19.33 46.83,19.62 46.86,19.65 46.86,19.74 47.07,19.95 47.15,19.95 47.18,19.98 47.47,19.98 47.83,20.33 47.83,20.62 49.33,22.13 49.33,30.08 52.25,33 52.25,37.3 51.67,37.88 v1(51.39,37.88)
  BOTTOM w0.152: U3.G3 v1(51.39,37.88)
DDR3_DQS2_P: length 45.9
  TOP w0.152: U1.P25 v1(33.22,18.59)
  L3_SIG w0.13: v1(51.39,37.08) 51.22,37.08 51.11,37.19 51.11,37.38 51.21,37.47 51.71,37.47 52,37.19 52,33.11 49.07,30.19 49.07,22.23 47.57,20.73 47.57,20.44 47.36,20.23 47.07,20.23 47.04,20.2 46.96,20.2 46.6,19.84 46.6,19.76 46.57,19.73 46.57,19.44 46.36,19.23 45.96,19.23 45.57,18.84 45.57,18.44 45.36,18.23 44.96,18.23 44.57,17.84 44.57,17.44 44.26,17.13 41.07,17.13 40.83,17.37 40.83,17.84 40.47,18.2 40.1,18.2 39.86,18.44 39.86,18.81 39.44,19.23 39.07,19.23 38.86,19.44 38.86,19.81 38.47,20.2 38.1,20.2 38.07,20.23 38.07,20.23 37.86,20.44 37.86,20.45 37.86,20.81 37.47,21.2 34.96,21.2 33.96,20.2 33.96,17.63 33.45,17.13 33.05,17.13 32.83,17.35 32.83,18.64 32.95,18.75 33.05,18.75 v1(33.22,18.59)
  BOTTOM w0.152: U3.F3 v1(51.39,37.08)
DDR3_DQS3_N: length 43.6
  TOP w0.152: U1.W25 v1(28.22,18.59)
  L18_SIG w0.13: v1(28.22,18.59) 28.59,18.96 31.29,18.96 31.31,18.95 31.49,18.95 31.51,18.96 31.78,19.23 31.78,19.29 31.83,19.33 31.83,19.52 31.86,19.55 31.86,19.74 32.07,19.94 32.19,19.94 32.22,19.98 32.47,19.98 32.83,20.33 32.83,20.55 32.83,20.55 32.83,20.71 33.09,20.98 33.47,20.98 33.83,21.33 33.83,21.34 34.39,21.9 34.39,22.52 34.84,22.98 38.47,22.98 38.83,23.33 38.83,23.71 39.07,23.94 39.44,23.94 39.83,24.33 39.83,24.79 40.01,24.98 47.46,24.98 49.54,22.9 52.45,22.9 52.81,23.26 52.81,23.4 53.39,23.98 53.39,29.45 53.39,29.45 53.39,30.86 53.92,31.39 53.92,33.91 54.16,34.14 55.13,34.14 v1(55.39,33.88)
  BOTTOM w0.152: U3.B7 v1(55.39,33.88)
DDR3_DQS3_P: length 43.6
  TOP w0.152: U1.W24 v1(28.22,19.59)
  L18_SIG w0.13: v1(28.22,19.59) 28.59,19.22 31.35,19.22 31.57,19.44 31.57,19.69 31.6,19.72 31.6,19.84 31.96,20.2 32.08,20.2 32.11,20.23 32.36,20.23 32.57,20.44 32.57,20.82 32.99,21.23 33.36,21.23 33.57,21.44 33.57,21.45 34.13,22.01 34.13,22.63 34.73,23.23 38.36,23.23 38.57,23.44 38.57,23.81 38.96,24.2 39.33,24.2 39.57,24.44 39.57,24.9 39.91,25.23 47.57,25.23 49.64,23.16 52.34,23.16 52.55,23.37 52.55,23.5 53.14,24.09 53.14,29.55 53.14,29.55 53.14,30.97 53.67,31.5 53.67,34.02 54.05,34.4 55.11,34.4 55.33,34.61 v1(55.39,34.61)
  BOTTOM w0.152: v1(55.39,34.61) 55.39,34.68 U3.C7
DDR3_ODT: length 52.6
  TOP w0.197: U1.Y22 v1(27.22,21.59) ; R162.1 50.1,40.73 49.79,41.04 v1(49.79,41.08)
  L3_SIG w0.14: v1(49.79,41.08) 50.95,39.92 51.94,39.92 53.9,37.95 53.9,33 53.63,32.73 53.63,32.67 53.46,32.49 53.46,25.83 52.38,24.75 50.22,24.75 49.79,24.32 v1(49.79,24.31)
  L18_SIG w0.14: v1(27.22,21.59) 27.22,21.59 27.61,21.19 29.39,21.19 29.85,21.66 29.85,21.74 30.07,21.95 30.09,21.95 30.58,22.44 30.58,22.5 31.3,23.23 31.37,23.23 31.58,23.44 31.58,23.5 32.3,24.23 32.37,24.23 32.58,24.44 32.58,24.5 33.07,25 38.14,25 38.58,25.44 38.58,25.68 39.12,26.23 39.37,26.23 39.58,26.44 39.58,26.68 40.06,27.16 47.16,27.16 47.58,26.74 47.58,26.53 v1(49.79,24.31)
  BOTTOM w0.197: U3.K1 v1(49.79,41.08) ; U2.K1 v1(49.79,24.31)
DDR3_RAS#: length 54.3
  TOP w0.197: R156.1 51.8,39.77 51.74,39.71 51.46,39.71 51.32,39.85 51.32,40.21 v1(51.39,40.28) ; U1.V23 v1(29.22,20.59)
  L3_SIG w0.14: v1(52.19,23.51) 52.19,23.55 53.72,25.08 53.72,27.24 53.9,27.41 53.9,32.62 54.28,33 54.28,38.1 53.93,38.45 53.93,38.56 53.9,38.59 53.9,39.99 53.14,40.75 51.86,40.75 v1(51.39,40.28)
  L14_SIG w0.14: v1(29.22,20.59) 29.6,20.59 30.14,20.05 30.41,20.05 30.66,20.3 30.66,20.81 30.41,21.06 29.9,21.06 29.77,21.19 29.77,22.71 30.28,23.22 33.96,23.22 34.59,23.85 34.85,24.12 34.85,24.74 35.07,24.95 36.37,24.95 36.85,24.46 36.85,24.44 37.07,24.23 37.09,24.23 37.2,24.11 37.87,24.11 37.98,23.99 47.93,23.99 48.77,23.15 49.94,23.15 50.9,24.11 51.1,24.11 51.26,24.27 51.46,24.27 51.64,24.08 51.64,23.89 51.54,23.79 51.54,23.59 51.62,23.51 v1(52.19,23.51)
  BOTTOM w0.197: U3.J3 v1(51.39,40.28) ; U2.J3 v1(52.19,23.51)
DDR3_RST#: length 86.1
  TOP w0.197: U1.H22 v1(40.22,21.59) ; R133.1 52.1,45.76 v1(52.1,45.96)
  L15_SIG w0.14: v1(50.59,45.88) 50.6,45.88 50.97,45.5 51.64,45.5 v1(52.1,45.96)
  L18_SIG w0.14: v1(50.59,45.88) 50.13,46.34 49.33,46.34 48.69,45.7 48.69,45.07 47.93,44.3 47.93,34.14 49.58,32.49 49.58,30.58 50.59,29.57 v1(50.59,29.11)
  BOTTOM w0.197: U2.T2 v1(50.59,29.11) 50.6,29.12 50.6,29.7 50.34,29.95 48.82,29.95 48.57,30.21 48.57,35.03 48.82,35.29 49.07,35.29 49.33,35.54 49.33,36.3 49.07,36.56 48.82,36.56 48.57,36.81 48.57,38.72 48.82,38.97 49.07,38.97 49.33,39.22 49.33,39.61 49.07,39.86 48.82,39.86 48.57,40.11 48.57,41.85 48.56,41.86 48.56,42.18 48.57,42.19 48.57,44.56 48.31,44.81 47.93,44.81 47.68,44.56 47.68,31.12 47.71,31.09 47.71,30.09 47.68,30.05 47.68,29.45 47.93,29.19 48.44,29.19 48.69,28.94 48.69,23.73 48.44,23.48 48.06,23.48 47.8,23.73 47.8,27.79 47.55,28.05 40.18,28.05 40.11,27.98 40.05,27.98 39.68,27.6 39.68,22.21 40.22,21.67 v1(40.22,21.59) ; v1(50.59,45.88) U3.T2
DDR3_WE#: length 60.5
  TOP w0.197: R155.1 51.8,41.62 51.67,41.49 51.16,41.49 51.07,41.57 51.07,41.85 51.08,41.87 51.38,41.87 v1(51.39,41.88) ; U1.V22 v1(29.22,21.59)
  L7_SIG w0.14: v1(29.22,21.59) 29.59,21.22 29.59,17.31 30.79,16.11 31.55,16.11 31.8,15.86 32.83,15.86 32.95,15.98 34.09,15.98 34.45,16.34 34.45,16.35 34.85,16.75 34.85,17.74 35.34,18.23 35.37,18.23 35.58,18.44 35.58,18.46 36.13,19.02 37.16,19.02 37.37,19.23 38.37,19.23 38.85,19.72 38.85,19.74 39.07,19.95 39.09,19.95 39.85,20.72 39.85,20.74 40.07,20.95 40.09,20.95 40.85,21.72 40.85,21.74 41.07,21.95 41.09,21.95 41.85,22.72 41.85,22.74 42.07,22.95 42.09,22.95 42.85,23.72 42.85,23.74 43.08,23.96 43.7,23.96 43.95,24.22 49.18,24.22 49.64,24.68 51.67,24.68 51.93,24.94 52.02,24.94 v1(52.19,25.11)
  L17_SIG w0.14: v1(52.19,25.11) 52.21,25.13 v1(54.28,25.13)
  BOTTOM w0.127: U3.L3 52.22,41.48 52.23,41.49 52.52,41.49 52.53,41.48 52.73,41.48
  BOTTOM w0.197: U2.L3 v1(52.19,25.11) ; v1(51.39,41.88) U3.L3 ; v1(54.28,25.13) 54.28,24.75 53.98,24.44 53.57,24.44 53.27,24.75 53.27,29.7 53.01,29.95 52.83,29.95 52.76,30.02 51.54,30.02 51.36,30.21 51.36,31.86 51.61,32.11 53.01,32.11 53.27,32.37 53.27,40.94 52.73,41.48
DX_0_N: length 57.8
  TOP w0.089: U1.R13 v1(32.22,31.59)
  L15_SIG w0.089: v1(32.22,31.59) 32.18,31.56 32.18,30.97 32.44,30.72 33.58,30.72 34.47,31.6 34.47,32.68 34.97,33.18 35.28,33.18 35.63,33.52 35.63,33.83 35.97,34.18 36.28,34.18 36.63,34.52 36.63,34.83 36.97,35.18 37.28,35.18 37.55,35.45 37.55,35.76 37.97,36.18 39.28,36.18 39.55,36.45 39.55,36.76 39.97,37.18 40.28,37.18 40.63,37.52 40.63,37.83 40.97,38.18 41.28,38.18 41.63,38.52 41.63,38.83 41.97,39.18 42.28,39.18 42.55,39.45 42.55,39.76 42.97,40.18 44.28,40.18 44.55,40.45 44.55,43.97 44.99,44.41 48.57,44.41 48.95,44.79 48.95,45.87 49.54,46.46 49.55,46.47 50.04,46.47 50.04,46.46 50.34,46.46 50.35,46.47 50.84,46.47 50.84,46.46 51.14,46.46 51.15,46.47 51.78,46.47 51.85,46.55 52.34,46.55 52.42,46.46 55.14,46.46 55.15,46.47 55.64,46.47 55.64,46.46 55.94,46.46 55.95,46.47 56.44,46.47 56.44,46.46 65.15,46.46 65.35,46.25 65.69,46.25 65.9,46.47 67.64,46.47 68.25,47.08 68.25,50.63 68.91,51.29 69.9,51.29 70.16,51.04 v1(70.16,49.69)
  BOTTOM w0.089: v1(70.16,49.69) 70.03,49.81 70.03,50.02 70.33,50.32 JX1.100
DX_0_P: length 57.8
  TOP w0.089: U1.R14 v1(32.22,29.59)
  L15_SIG w0.089: v1(32.22,29.59) 32.18,29.62 32.18,30.08 32.56,30.46 33.69,30.46 34.72,31.5 34.72,32.57 35.08,32.92 35.39,32.92 35.88,33.42 35.88,33.73 36.08,33.92 36.39,33.92 36.88,34.42 36.88,34.73 37.08,34.92 37.39,34.92 37.88,35.42 37.88,35.73 38.08,35.92 39.39,35.92 39.88,36.42 39.88,36.73 40.08,36.92 40.39,36.92 40.88,37.42 40.88,37.73 41.08,37.92 41.39,37.92 41.88,38.42 41.88,38.73 42.08,38.92 42.39,38.92 42.88,39.42 42.88,39.73 43.08,39.92 44.39,39.92 44.81,40.34 44.81,43.87 45.1,44.16 48.67,44.16 49.2,44.69 49.2,45.76 49.65,46.21 49.93,46.21 49.94,46.21 50.45,46.21 50.45,46.21 50.73,46.21 50.74,46.21 51.25,46.21 51.25,46.21 51.88,46.21 51.96,46.29 52.24,46.29 52.32,46.21 55.25,46.21 55.25,46.21 55.53,46.21 55.54,46.21 56.05,46.21 56.05,46.21 56.33,46.21 56.34,46.21 65.04,46.21 65.25,46 65.79,46 66.01,46.22 67.75,46.22 68.51,46.97 68.51,50.53 69.01,51.04 69.8,51.04 69.9,50.93 69.9,50.78 69.72,50.6 69.62,50.6 69.53,50.52 69.53,50.31 69.6,50.25 69.71,50.25 69.78,50.18 69.78,49.94 v1(69.52,49.69)
  BOTTOM w0.089: v1(69.52,49.69) 69.54,49.69 69.75,49.89 69.75,50.02 69.53,50.24 JX1.98
ETH_MD1_N: length 31.4
  L7_SIG w0.089: v1(16.31,11.92) 16.31,12.94 15.17,14.08 15.17,17.56 14.96,17.77 14.96,18.26 15.17,18.47 15.17,19.01 15.67,19.52 15.67,26.55 15.44,26.78 14.55,26.78 11.63,29.7 9.22,29.7 8.43,30.48 8.43,31.58 8.96,32.11 v1(9.58,32.11)
  BOTTOM w0.089: v1(9.58,32.11) 9.32,31.86 9.2,31.86 8.88,32.17 JX3.53 ; U10.27 17.35,9.84 17.14,10.05 16.98,10.05 16.73,10.31 16.73,11.32 16.54,11.51 16.54,11.69 v1(16.31,11.92)
ETH_MD1_P: length 31.5
  L7_SIG w0.089: v1(9.58,31.48) 9.32,31.73 8.94,31.73 8.69,31.48 8.69,30.59 9.32,29.95 11.74,29.95 14.66,27.03 15.55,27.03 15.93,26.65 15.93,19.41 15.42,18.9 15.42,18.36 15.21,18.15 15.21,17.88 15.42,17.67 15.42,14.18 16.56,13.04 16.56,12.14 16.64,12.06 16.64,11.65 16.72,11.57 16.85,11.57 16.94,11.67 v1(16.94,11.92)
  BOTTOM w0.089: v1(9.58,31.48) 9.41,31.64 9.2,31.64 8.93,31.37 JX3.51 ; U10.28 17.27,10.34 17.2,10.27 17.07,10.27 16.94,10.4 16.94,11.41 16.75,11.6 16.75,11.73 v1(16.94,11.92)
ETH_MD2_N: length 29.7
  L7_SIG w0.089: v1(19.19,10.14) 19.19,10.56 18.59,11.16 18.59,11.57 18.8,11.78 18.8,12.06 18.59,12.27 18.59,28.56 15.17,31.99 14.15,31.99 v1(14.02,32.11)
  BOTTOM w0.089: v1(14.02,32.11) 13.98,32.11 13.82,31.95 13.64,31.95 13.42,32.17 JX3.54 ; U10.23 17.91,7.84 18.05,7.99 18.27,7.99 18.68,8.4 18.68,9.42 18.94,9.67 18.94,9.89 v1(19.19,10.14)
ETH_MD2_P: length 29.7
  L7_SIG w0.089: v1(14.02,31.6) 14.15,31.73 15.06,31.73 18.34,28.45 18.34,12.27 18.13,12.06 18.13,11.78 18.34,11.57 18.34,11.05 18.84,10.55 18.84,10.01 18.72,9.89 18.6,9.89 18.47,10.02 v1(18.47,10.14)
  BOTTOM w0.089: U10.24 17.92,8.34 18.06,8.2 18.18,8.2 18.47,8.49 18.47,9.51 18.72,9.76 18.72,9.89 v1(18.47,10.14) ; JX3.52 13.28,31.37 13.64,31.73 13.9,31.73 v1(14.02,31.6)
ETH_MD3_N: length 43.8
  L7_SIG w0.089: v1(6.02,34.27) 6.02,34.02 5.89,33.89 4.24,33.89 3.65,33.3 3.65,27.62 5.26,26.02 5.26,23.73 7.8,21.19 7.8,14.46 8.05,14.21 11.61,14.21 11.86,13.95 11.86,10.54 12.37,10.04 12.37,9.33 11.91,8.86 11.91,7.53 12.59,6.84 14.91,6.84 15.67,7.6 15.67,8.44 15.76,8.53 15.89,8.53 15.93,8.49 v1(16.31,8.49)
  BOTTOM w0.089: v1(16.31,8.49) 16.6,8.2 16.6,7.39 16.98,7 17.14,7 17.3,6.84 U10.21 ; v1(6.02,34.27) 5.72,34.27 5.46,34.53 JP2.1
ETH_MD3_P: length 43.8
  L7_SIG w0.089: v1(16.82,8.49) 16.74,8.57 16.74,8.72 16.63,8.83 15.93,8.83 15.89,8.79 15.66,8.79 15.42,8.55 15.42,7.71 14.81,7.09 12.7,7.09 12.16,7.63 12.16,8.76 12.63,9.22 12.63,10.14 12.12,10.65 12.12,14.06 11.71,14.46 8.16,14.46 8.05,14.56 8.05,21.3 5.51,23.84 5.51,26.12 3.91,27.73 3.91,33.19 4.35,33.64 5.89,33.64 6.02,33.51 v1(6.02,33)
  BOTTOM w0.089: v1(16.82,8.49) 16.82,7.48 17.07,7.22 17.2,7.22 17.32,7.34 U10.22 ; JP1.1 5.46,32.82 5.64,33 v1(6.02,33)
ETH_MD4_N: length 39.8
  L7_SIG w0.089: v3(10.34,26.27) 10.47,26.4 11,26.4 13.07,24.32 13.07,19.16 12.75,18.84 12.75,12.7 13.07,12.39 13.07,8.76 12.88,8.57 v1(12.88,8.24)
  L17_SIG w0.089: v1(14.91,32.87) 14.91,32.01 15,31.92 15.19,31.92 15.26,31.86 16.16,31.86 16.56,31.46 16.56,30.36 15.91,29.7 15.27,29.7 11.97,26.4 10.8,26.4 10.67,26.27 v3(10.34,26.27)
  BOTTOM w0.089: v1(12.88,8.24) 13.13,7.99 13.13,7.89 13.43,7.59 13.43,5.64 13.97,5.1 16.35,5.1 16.47,4.97 17.14,4.97 17.27,4.84 U10.17 ; JP4.1 v1(14.91,32.87)
ETH_MD4_P: length 39.8
  L7_SIG w0.089: v3(10.34,26.78) 10.47,26.65 11.1,26.65 13.32,24.43 13.32,19.05 13.01,18.74 13.01,12.81 13.32,12.49 13.32,8.76 13.51,8.57 v1(13.51,8.24)
  L17_SIG w0.089: v3(10.34,26.78) 10.67,26.78 10.8,26.65 11.86,26.65 15.17,29.95 15.8,29.95 16.31,30.46 16.31,31.35 16.05,31.6 15.15,31.6 15.09,31.67 14.72,31.67 14.4,31.35 14.4,30.97 14.66,30.72 v1(14.91,30.72)
  BOTTOM w0.089: JP3.1 14.96,30.66 v1(14.91,30.72) ; U10.18 17.35,5.34 17.2,5.19 16.56,5.19 16.44,5.32 14.06,5.32 13.64,5.73 13.64,7.68 13.34,7.98 13.34,8.07 v1(13.51,8.24)
ETH_PHY_LED0: length 26.6
  TOP w0.14: R18.2 v5(1.83,51.16)
  L17_SIG w0.095: v5(1.83,51.16) 3.23,49.77 3.23,39.22 3.74,38.72 5.01,38.72 6.02,37.7 6.02,37.32 7.29,36.05 7.29,31.99 6.84,31.53 v1(6.84,29.77)
  BOTTOM w0.14: JX3.47 v1(6.84,29.77)
ETH_PHY_LED1: length 40.1
  TOP w0.14: v1(37.64,14.84) 37.77,14.71 37.77,14.08 R17.2
  L7_SIG w0.095: v1(37.64,14.84) 31.8,14.84 31.17,15.48 28.12,15.48 26.6,17 26.6,24.75 26.34,25 26,25 25.71,25.3 25.71,25.64 25.2,26.14 20.12,26.14 19.1,27.16 19.1,29.06 v1(19.61,29.57)
  L14_SIG w0.095: v1(14.15,30.46) 14.66,29.95 19.23,29.95 v1(19.61,29.57)
  BOTTOM w0.14: v1(14.15,30.46) 13.46,29.77 JX3.48
FB0V95: length 4.1
  TOP w0.14: R49.2 22.91,11.09 R302.2 ; R302.2 24.18,11.09 R303.1 ; R302.2 23.55,10.2 23.52,10.17 23.52,9.32 23.66,9.17 U18.2
FB1V0: length 5.9
  TOP w0.14: v2(58.75,11.62) 58.75,11.6 58.85,11.5 58.85,11.48 59.1,11.23 59.1,11.17 59.25,11.02 U4.11
  L2_GND w0.203: v3(58.54,11.98) 58.73,11.79 58.73,11.65 v2(58.75,11.62)
  L19_GND w0.203: v4(59.23,12.68) v3(58.54,11.98)
  BOTTOM w0.14: R47.2 59.23,14.46 59.34,14.36 59.34,13.97 59.87,13.44 59.87,12.87 R20.1 v4(59.23,12.68) 59.17,12.74 R23.1
FB1V8: length 24.6
  TOP w0.14: U4.23 60.75,6.6 61.28,6.06 v2(62.41,6.06)
  L2_GND w0.203: v2(62.41,6.06) v3(62.9,6.06)
  L3_SIG w0.095: v1(62.03,15.6) 62.5,15.13 65.14,15.13 66,14.27 66,13.51 65.2,12.71 65.2,8.87 64.31,7.98 64.31,7.47 v3(62.9,6.06)
  L15_SIG w0.095: v1(62.03,3.79) 62.03,5.19 v3(62.9,6.06)
  BOTTOM w0.14: R22.1 63.3,18.78 63.3,16.75 62.92,16.36 R25.1 62.83,15.31 62.54,15.6 v1(62.03,15.6) ; R46.2 v1(62.03,3.79)
FB1V35: length 14.7
  TOP w0.14: U4.8 v2(60.75,11.53) ; v1(54.54,14.21) 54.54,14.71 55.01,15.18 R24.1
  L2_GND w0.203: v2(60.75,11.53) 60.75,11.55 60.25,12.05 v3(60.25,12.55)
  L7_SIG w0.095: v1(60.63,15.86) 60.63,13.7 60.25,13.32 v3(60.25,12.55)
  L15_SIG w0.095: v3(60.25,12.55) 59.49,12.55 58.35,13.7 55.42,13.7 54.92,14.21 v1(54.54,14.21)
  BOTTOM w0.14: R21.1 54.54,13.95 v1(54.54,14.21) ; R48.2 v1(60.63,15.86)
FB_0V95: length 70.1
  TOP w0.14: v1(19.96,10.1) 20.55,9.51 21.77,9.51 22.17,9.91 22.17,10.14 22.49,10.46 R49.1
  L18_SIG w0.095: v1(15.42,49.51) 16.82,48.11 16.82,43.42 16.18,42.78 14.53,42.78 13.75,43.56 9.6,43.56 7.93,41.89 7.93,25.38 7.8,25.25 7.8,12.43 8.43,11.79 8.43,10.27 8.56,10.14 10.21,10.14 10.97,10.9 11.86,10.9 12.37,10.4 16.56,10.4 17.2,11.03 19.03,11.03 v1(19.96,10.1)
  BOTTOM w0.14: R45.2 17.71,51.29 C215.1 15.93,50.02 v1(15.42,49.51)
FB_1V0: length 87
  TOP w0.14: v1(15.42,46.21) 16.05,46.84 16.31,46.84 C209.1 R42.2
  L3_SIG w0.095: v3(59.87,47.48) 60,47.35 60,44.69 59.49,44.18 59.49,43.8 58.22,42.53 58.22,30.21 58.85,29.57 58.85,28.18 58.35,27.67 58.35,23.6 59.49,22.46 59.49,21.98 59.61,21.86 59.61,21.54 59.49,21.42 59.49,20.3 58.85,19.67 58.85,19.16 v1(59.36,18.65)
  L6_SIG w0.095: v3(59.87,47.48) 58.98,48.37 58.98,49.38 57.35,51.02 30.37,51.02 30.25,50.91 27.36,50.91 26.72,50.27 19.74,50.27 17.71,48.24 17.71,47.48 16.44,46.21 v1(15.42,46.21)
  BOTTOM w0.14: R47.1 59.36,16.36 v1(59.36,18.65)
FB_1V8: length 114.4
  L3_SIG w0.095: v3(61.01,47.48) 61.14,47.35 61.14,44.69 58.73,42.27 58.73,37.07 60.72,35.07 60.72,24.24 60.63,24.15 60.63,19.79 60.89,19.54 60.89,17 61.65,16.24 62.28,16.24 63.17,15.35 65.33,15.35 66.22,14.46 66.22,12.3 65.46,11.54 65.46,7.6 64.44,6.59 64.44,4.55 v1(63.68,3.79)
  L6_SIG w0.095: v3(18.59,52.69) 20.88,54.97 24.82,54.97 25.2,54.59 29.77,54.59 32.69,51.67 59.23,51.67 61.01,49.89 v3(61.01,47.48)
  L18_SIG w0.095: v1(18.59,42.4) 19.1,42.4 19.36,42.65 19.36,44.69 19.48,44.81 19.48,47.23 17.96,48.75 17.96,52.05 v3(18.59,52.69)
  BOTTOM w0.14: v1(18.59,42.4) 17.9,43.03 R41.2 16.44,43.1 C207.1 ; v1(63.68,3.79) R46.1
FB_1V35: length 79.9
  L3_SIG w0.095: v1(59.87,18.65) 59.49,18.27 58.85,18.27 57.84,19.29 57.84,28.56 58.22,28.94 58.22,29.45 57.84,29.83 57.84,47.1 v3(58.22,47.48)
  L6_SIG w0.095: v1(20.88,49.13) 21.39,48.62 26.47,48.62 27.99,50.15 31.17,50.15 31.68,50.65 55.55,50.65 56.57,49.64 56.57,48.88 57.96,47.48 v3(58.22,47.48)
  BOTTOM w0.14: v1(59.87,18.65) 59.87,18.52 R48.1 ; C213.1 16.44,46.84 17.07,47.48 17.07,47.86 R44.2 20.25,48.5 v1(20.88,49.13)
FPGA_DONE: length 31.6
  TOP w0.14: R172.2 37.64,48.75 35.23,51.16 35.23,52.94 34.72,53.45 v1(33.39,53.45) ; U1.W9 v1(28.22,35.59)
  L7_SIG w0.095: v1(28.22,35.59) 28.22,35.64 28.75,36.18 28.75,45.7 30.53,47.48 30.53,49.64 33.53,52.63 33.53,53.31 v1(33.39,53.45)
  BOTTOM w0.14: v1(33.39,53.45) 33.53,53.31 JX1.8
FPGA_VBATT: length 114.7
  TOP w0.14: R9.2 v1(24.94,49.38) ; U1.V15 v1(29.22,28.59)
  L7_SIG w0.203: v1(24.94,49.38) 25.45,48.88 25.45,47.1 27.61,44.94 27.61,31.35 27.99,30.97 29.14,30.97 29.77,30.33 29.77,29.06 29.29,28.59 v1(29.22,28.59)
  L14_SIG w0.203: v3(77.9,60.43) 52.04,60.43 52.03,60.42 51.71,60.42 51.69,60.43 49.2,60.43 48.44,59.67 47.34,59.67 47.33,59.66 46.5,59.66 46.49,59.67 35.99,59.67 33.53,57.21 v1(33.53,56.7) 33.53,56.19 27.23,49.89 25.96,49.89 25.45,49.38 v1(24.94,49.38)
  L15_SIG w0.203: v1(78.79,43.29) 79.81,44.3 80.44,44.3 80.82,44.69 80.82,47.61 79.68,48.75 74.98,48.75 74.47,49.26 74.47,50.65 77.33,53.51 78.09,53.51 79.05,54.46 79.05,55.23 79.94,56.12 79.94,60.05 79.55,60.43 v3(77.9,60.43)
  BOTTOM w0.14: JX1.7 v1(33.53,56.7)
  BOTTOM w0.254: v1(78.79,43.29) 78.79,43.67 78.52,43.94 U24.20
GPO0: length 42.2
  TOP w0.14: v6(64.4,25.69) U17.B7
  L7_SIG w0.095: v6(64.4,25.69) 64.75,25.69 66.05,26.99 66.12,26.99 66.3,27.17 66.3,27.24 66.85,27.79 66.92,27.79 67.1,27.97 67.1,28.04 67.65,28.59 67.72,28.59 67.9,28.77 67.9,28.84 69.01,29.95 70.16,29.95 73.2,33 73.2,35.67 73.59,36.05 73.59,43.92 76.89,47.23 76.89,48.24 79.56,50.91 80.82,50.91 81.16,50.57 v1(87.26,50.57)
  BOTTOM w0.14: JX4.1 v1(87.26,50.57)
GPO1: length 33.5
  TOP w0.14: v6(66,25.69) U17.B6
  L7_SIG w0.095: v6(66,25.69) 66,26.05 66.5,26.55 66.5,26.62 66.67,26.79 66.74,26.79 67.3,27.35 67.3,27.42 67.47,27.59 67.54,27.59 68.1,28.15 68.1,28.22 68.27,28.39 68.34,28.39 68.9,28.95 68.9,29.02 69.07,29.19 69.14,29.19 69.39,29.45 70.16,29.45 73.59,32.87 73.59,35.67 74.73,36.81 74.73,40.75 75.24,41.26 75.24,44.18 78.16,47.1 78.16,48.88 79.85,50.57 v1(80.06,50.57)
  BOTTOM w0.14: JX4.2 v1(80.06,50.57)
GPO2: length 40.1
  TOP w0.14: v6(66.8,25.69) U17.B5
  L7_SIG w0.095: v1(87.3,49.77) 86.93,50.15 79.81,50.15 78.79,49.13 78.79,46.84 75.62,43.67 75.62,41 75.24,40.62 75.24,36.68 73.97,35.41 73.97,32.58 69.82,28.43 69.01,28.43 68.7,28.11 68.7,27.97 68.52,27.79 68.38,27.79 67.9,27.31 67.9,27.17 67.72,26.99 67.58,26.99 67.1,26.51 67.1,26.37 66.8,26.07 v6(66.8,25.69)
  BOTTOM w0.14: JX4.3 v1(87.3,49.77)
GPO3: length 33.9
  TOP w0.14: v6(67.6,25.69) U17.B4
  L7_SIG w0.095: v6(67.6,25.69) 67.97,25.69 68.27,25.99 68.36,25.99 68.89,26.52 68.89,26.65 69.14,26.91 70.18,26.91 70.4,26.69 70.68,26.69 70.89,26.91 71.32,26.91 72.55,28.14 72.55,28.47 72.78,28.71 73.35,28.71 76.63,31.99 76.63,38.72 78.41,40.49 78.41,45.45 79.43,46.46 79.68,46.46 80.57,47.35 80.57,49.26 v1(80.06,49.77)
  BOTTOM w0.14: JX4.4 80.06,49.77 v1(80.06,49.77)
INIT_B_0_JX2_09: length 57.9
  TOP w0.14: R168.2 35.61,46.59 v1(35.36,46.34) ; U1.R8 v1(32.22,36.59)
  L15_SIG w0.095: v1(35.36,46.34) 34.98,46.34 32.56,43.91 32.56,37.45 32.31,37.2 32.31,36.68 v1(32.22,36.59)
  L18_SIG w0.095: v3(33.96,12.55) 33.07,12.55 32.22,13.4 32.22,13.7 32.15,13.77 32.15,13.92 30.37,15.7 29.35,15.7 28.78,16.28 28.78,16.82 28.56,17.04 28.56,17.73 28.36,17.93 27.83,17.93 27.61,18.14 27.61,19.67 27.36,19.93 26.84,19.93 26.6,20.17 26.6,22.97 26.88,23.25 28.36,23.25 28.55,23.45 28.55,23.73 29.07,24.25 29.36,24.25 29.55,24.45 29.55,24.73 30.07,25.25 30.36,25.25 30.66,25.55 30.66,25.89 30.92,26.15 32.61,26.15 32.65,26.2 32.65,26.82 32.98,27.15 38.4,27.15 38.65,27.41 38.65,27.82 38.79,27.95 38.79,29.83 37.37,31.25 37.07,31.25 36.88,31.45 36.88,31.74 36.37,32.25 36.07,32.25 35.88,32.45 35.88,32.74 35.56,33.06 35.56,33.73 35.21,34.07 35.21,34.11 34.88,34.45 34.88,35.26 33.89,36.25 33.07,36.25 32.73,36.59 v1(32.22,36.59)
  L19_GND w0.203: v4(34.33,12.19) v3(33.96,12.55)
  BOTTOM w0.14: JX2.9 v4(34.33,12.19)
IO_00_12_JX4: length 67.4
  TOP w0.14: U1.W14 v1(28.22,29.59)
  L14_SIG w0.095: v3(80.19,46.08) 80.19,47.99 79.05,49.13 75.74,49.13 72.7,46.08 69.06,46.08 66.65,43.67 64.19,43.67 62.85,42.34 62.25,42.34 61.77,41.86 61.77,41.38 61.13,40.74 55.25,40.74 55.05,40.94 55.05,40.94 54.48,41.51 47.62,41.51 47.36,41.25 47.07,41.25 46.88,41.45 46.56,41.45 46.36,41.25 45.39,41.25 43.88,39.73 43.88,39.61 43.19,38.93 43.07,38.93 41.88,37.73 41.88,37.61 41.33,37.07 39.04,37.07 38.79,36.81 38.79,36.43 38.53,36.18 38.28,36.18 37.55,35.45 37.55,35.45 37.36,35.25 37.1,35.25 36.76,34.91 36.76,33.38 36.5,33.13 34.97,33.13 34.34,32.5 34.34,30.46 34.09,30.21 28.88,30.21 28.26,29.59 v1(28.22,29.59)
  L19_GND w0.203: v3(80.19,46.08) 80.32,45.96 v4(80.57,45.96)
  BOTTOM w0.14: v4(80.57,45.96) 80.75,45.77
IO_00_13_JX2: length 30.2
  TOP w0.14: U1.V19 v1(29.22,24.59)
  L17_SIG w0.095: v1(37.26,13.19) 35.99,13.19 34.85,12.05 32.95,12.05 v3(32.44,12.55)
  L18_SIG w0.095: v1(29.22,24.59) 28.8,25 27.1,25 26.55,24.45 26.55,24.45 25.07,22.97 25.07,22.93 24.88,22.73 24.88,19.45 25.07,19.25 26.38,19.25 26.72,18.9 26.72,18.88 26.88,18.72 26.88,17.45 27.27,17.05 28.23,17.05 28.55,16.72 28.55,16.18 29.26,15.48 30.28,15.48 31.93,13.82 31.93,13.06 v3(32.44,12.55)
  BOTTOM w0.14: JX2.13 35.93,12.74 36.37,13.19 v1(37.26,13.19)
IO_00_33_JX1: length 73
  TOP w0.14: U1.L9 v1(37.22,35.59)
  L17_SIG w0.095: v1(37.22,35.59) 37.22,35.59 36.76,36.05 36.12,36.05 35.61,36.56 35.61,39.73 35.1,40.25 35.07,40.25 34.26,41.07 34.26,45.08 33.64,45.7 22.91,45.7 22.53,46.08 22.53,48.37 22.91,48.75 32.31,48.75 32.56,49 43.36,49 43.61,49.26 43.61,49.89 43.87,50.15 44.76,50.15 45.01,50.4 45.01,51.04 44.76,51.29 31.93,51.29 31.55,51.67 31.55,55.35 31.93,55.73 33.95,55.73 34.33,56.12 v1(34.33,56.74)
  BOTTOM w0.14: JX1.9 v1(34.33,56.74)
IO_00_34_AD9361_CLKSEL: length 62.7
  TOP w0.14: U1.K11 v1(38.22,33.59) ; v1(82.09,54.59) 82.6,55.1 84.25,55.1 84.61,55.46 Q6.1
  L7_SIG w0.095: v1(82.09,54.59) 77.4,49.89 v1(76.51,49.89) 76.51,49.26 v3(74.73,47.48)
  L14_SIG w0.095: v1(38.22,33.59) 37.77,34.03 37.77,34.78 38.03,35.03 38.41,35.03 38.79,35.41 38.79,35.8 39.04,36.05 41.16,36.05 44.56,39.45 44.56,39.53 45.14,40.11 48.31,40.11 48.95,40.75 49.64,40.75 49.65,40.74 54.29,40.74 55.09,39.94 61.09,39.94 61.52,40.37 63.55,40.37 63.93,40.75 63.93,42.15 64.31,42.53 66.09,42.53 68.25,44.69 72.7,44.69 74.47,46.46 74.47,47.23 v3(74.73,47.48)
  BOTTOM w0.14: R54.1 75.49,50.4 75.49,50.02 75.62,49.89 v1(76.51,49.89)
IO_00_35_AD9361_RST: length 39.2
  TOP w0.14: U1.H16 v1(40.22,27.59) ; v6(66.8,32.89) U17.K5
  L6_SIG w0.095: v1(40.22,27.59) 40.22,27.19 39.68,26.65 39.68,26.52 39.3,26.14 38.15,26.14 37.64,26.65 37.64,28.68 38.03,29.06 39.3,29.06 39.88,29.65 39.88,29.73 40.07,29.93 40.26,29.93 40.86,30.53 40.86,30.73 41.06,30.93 41.26,30.93 41.51,31.18 49.21,31.18 49.3,31.1 56.98,31.1 57.06,31.01 57.37,31.01 57.71,31.35 57.71,31.6 58.6,32.49 59.11,32.49 59.87,31.73 66.09,31.73 66.47,32.11 66.47,32.57 v6(66.8,32.89)
